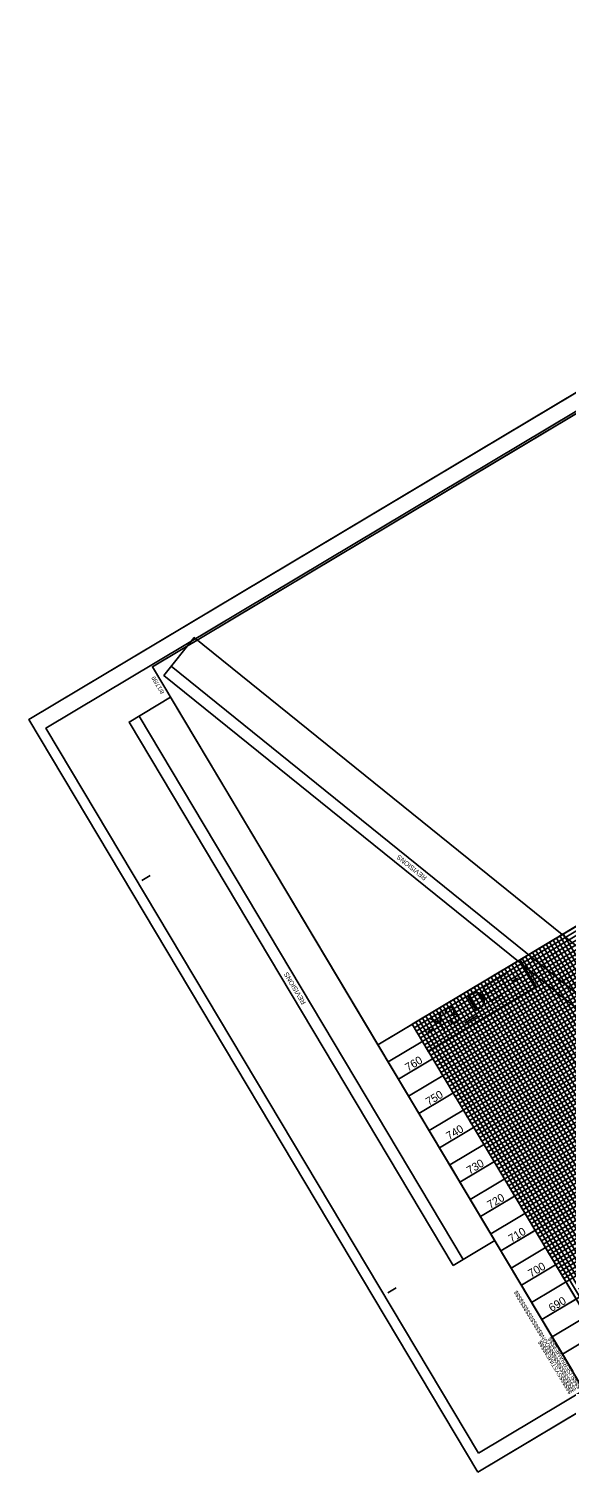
# Model space of a CAD drawing. Extents: x 1487794 to 1489801, y 498102 to 499906.
# Drawn here: x 1487794 to 1488466, y 498102 to 499906 of the extents above; entities that cross this region are included whole.
import ezdxf

# ---------------------------------------------------------------- set-up
doc = ezdxf.new("R2010")
doc.units = 0
for name, color, linetype in [('Exist Vertical Profile Ground Line', 7, 'Continuous'), ('Exist Vertical Profile Horizontal Axis Label Major', 7, 'Continuous'), ('Exist Vertical Profile Vertical Axis Label', 7, 'Continuous'), ('Prop Horizontal Alignment Curve and Spiral Data', 7, 'Continuous'), ('Prop Terminator CELL', 7, 'Continuous'), ('Prop Vertical Profile Curve Label', 7, 'Continuous'), ('Scratch_Level_6', 7, 'Continuous'), ('Sheet Data Field CELL', 7, 'Continuous'), ('Sheet DOT Grid CELL', 7, 'Continuous'), ('Sheet Layout Profile Border Port 2', 7, 'Continuous'), ('Sheet Plot Border Inside CELL', 7, 'Continuous'), ('Sheet Plot Border Outside CELL', 7, 'Continuous'), ('Sheet Profile CELL', 7, 'Continuous'), ('Sheet Profile Grid Major CELL', 7, 'Continuous'), ('Sheet Profile Grid Middle CELL', 7, 'Continuous'), ('Sheet Sticker Incomplete CELL', 7, 'Continuous')]:
    doc.layers.add(name, color=color, linetype=linetype)

msp = doc.modelspace()

# ---------------------------------------------------------------- linework, layer by layer
at = {"layer": 'Exist Vertical Profile Ground Line'}
msp.add_lwpolyline([(1488356.6, 498126.2), (1489787, 498980.3), (1489246.1, 499886.1), (1487815.7, 499032)], close=True, dxfattribs=at)
at = {"layer": 'Exist Vertical Profile Horizontal Axis Label Major'}
msp.add_lwpolyline([(1488355.7, 498102.3), (1489801.1, 498965.4), (1489239.8, 499905.6), (1487794.3, 499042.5)], close=True, dxfattribs=at)
at = {"layer": 'Exist Vertical Profile Vertical Axis Label'}
for p, q in [((1489239.8, 499905.6), (1487794.3, 499042.5)), ((1487794.3, 499042.5), (1488355.7, 498102.3)), ((1488355.7, 498102.3), (1489801.1, 498965.4))]:
    msp.add_line(p, q, dxfattribs=at)
at = {"layer": 'Prop Horizontal Alignment Curve and Spiral Data'}
msp.add_lwpolyline([(1488273.7, 498661.9), (1489475.7, 499379.7), (1489719.2, 498971.8), (1488517.2, 498254.1)], close=True, dxfattribs=at)
at = {"layer": 'Prop Terminator CELL'}
msp.add_lwpolyline([(1488230.8, 498636.3), (1487948.8, 499108.5), (1489064.9, 499775), (1489153.9, 499626), (1489135, 499614.7), (1489151.4, 499587.3), (1489342, 499701.1), (1489518.7, 499405.3)], close=True, dxfattribs=at)
at = {"layer": 'Prop Vertical Profile Curve Label'}
msp.add_lwpolyline([(1488293.7, 498628.4), (1488428.7, 498709), (1488408.7, 498742.5), (1488273.7, 498661.9)], close=True, dxfattribs=at)
at = {"layer": 'Scratch_Level_6'}
for p, q in [((1488587.8, 498612.8), (1487972.3, 499109.2)), ((1488337.4, 498368), (1487932.1, 499046.9))]:
    msp.add_line(p, q, dxfattribs=at)
for points in [[(1488578.7, 498601.5), (1487963.2, 499097.8), (1488001.2, 499145), (1488616.7, 498648.6)], [(1488324.9, 498360.6), (1487919.6, 499039.4), (1487971.5, 499070.5), (1488376.9, 498391.6)]]:
    msp.add_lwpolyline(points, close=True, dxfattribs=at)
at = {"layer": 'Sheet Data Field CELL'}
msp.add_line((1488273.7, 498661.9), (1488316.6, 498687.6), dxfattribs=at)
for points in [[(1488230.8, 498636.3), (1489518.7, 499405.3)], [(1489544.3, 499362.4), (1488256.4, 498593.4), (1488282, 498550.4), (1489569.9, 499319.5)], [(1489595.6, 499276.5), (1488307.7, 498507.5), (1488333.3, 498464.6), (1489621.2, 499233.6)], [(1489646.8, 499190.7), (1488358.9, 498421.7), (1488384.6, 498378.7), (1489672.5, 499147.7)], [(1489698.1, 499104.8), (1488410.2, 498335.8), (1488435.8, 498292.9), (1489723.7, 499061.9)], [(1489749.4, 499018.9), (1488461.5, 498249.9)], [(1488688.9, 498356.6), (1488445.4, 498764.5), (1488488.4, 498790.1), (1488731.9, 498382.3)], [(1488603.1, 498305.4), (1488359.6, 498713.2), (1488402.5, 498738.8), (1488646, 498331)], [(1488517.2, 498254.1), (1488273.7, 498661.9), (1488316.6, 498687.6), (1488560.2, 498279.7)], [(1488230.8, 498636.3), (1488474.3, 498228.5)]]:
    msp.add_lwpolyline(points, dxfattribs=at)
at = {"layer": 'Sheet Plot Border Inside CELL'}
for p, q in [((1488243.6, 498614.8), (1489531.5, 499383.8)), ((1489557.1, 499340.9), (1488269.2, 498571.9)), ((1488294.9, 498529), (1489582.7, 499298)), ((1489608.4, 499255.1), (1488320.5, 498486.1)), ((1488346.1, 498443.1), (1489634, 499212.1)), ((1489659.6, 499169.2), (1488371.8, 498400.2)), ((1488397.4, 498357.3), (1489685.3, 499126.3)), ((1489710.9, 499083.3), (1488423, 498314.3)), ((1488448.7, 498271.4), (1489736.5, 499040.4)), ((1488269.2, 498571.9), (1488294.9, 498529)), ((1488320.5, 498486.1), (1488346.1, 498443.1)), ((1488371.8, 498400.2), (1488397.4, 498357.3)), ((1488423, 498314.3), (1488448.7, 498271.4))]:
    msp.add_line(p, q, dxfattribs=at)
for points in [[(1488624.5, 498318.2), (1488381, 498726), (1488424, 498751.7), (1488667.5, 498343.8)], [(1488538.7, 498266.9), (1488295.2, 498674.8), (1488338.1, 498700.4), (1488581.6, 498292.6)]]:
    msp.add_lwpolyline(points, dxfattribs=at)
at = {"layer": 'Sheet Plot Border Outside CELL'}
for p, q in [((1488230.8, 498636.3), (1489518.7, 499405.3)), ((1488256.4, 498593.4), (1489544.3, 499362.4)), ((1488282, 498550.4), (1489569.9, 499319.5)), ((1488307.7, 498507.5), (1489595.6, 499276.5)), ((1488333.3, 498464.6), (1489621.2, 499233.6)), ((1488358.9, 498421.7), (1489646.8, 499190.7)), ((1488384.6, 498378.7), (1489672.5, 499147.7)), ((1488410.2, 498335.8), (1489698.1, 499104.8)), ((1488435.8, 498292.9), (1489723.7, 499061.9)), ((1488461.5, 498249.9), (1489749.4, 499018.9)), ((1488445.4, 498764.5), (1488688.9, 498356.6)), ((1488402.5, 498738.8), (1488646, 498331)), ((1488359.6, 498713.2), (1488603.1, 498305.4)), ((1488316.6, 498687.6), (1488560.2, 498279.7)), ((1488273.7, 498661.9), (1488517.2, 498254.1))]:
    msp.add_line(p, q, dxfattribs=at)
at = {"layer": 'Sheet Profile CELL'}
msp.add_lwpolyline([(1488273.7, 498661.9), (1489475.7, 499379.7), (1489719.2, 498971.8), (1488517.2, 498254.1)], close=True, dxfattribs=at)
at = {"layer": 'Sheet Profile Grid Major CELL'}
for points in [[(1489478.3, 499375.4), (1488276.3, 498657.6)], [(1489483.4, 499366.8), (1488281.4, 498649.1), (1488278.8, 498653.4), (1489480.9, 499371.1)], [(1489491.1, 499353.9), (1488289.1, 498636.2), (1488286.5, 498640.5), (1488284, 498644.8), (1489486, 499362.5)], [(1489496.2, 499345.3), (1488294.2, 498627.6), (1488291.7, 498631.9), (1489493.7, 499349.6)], [(1489503.9, 499332.5), (1488301.9, 498614.7), (1488299.3, 498619), (1488296.8, 498623.3), (1489498.8, 499341)], [(1489509.1, 499323.9), (1488307, 498606.1), (1488304.5, 498610.4), (1489506.5, 499328.2)], [(1489516.7, 499311), (1488314.7, 498593.3), (1488312.2, 498597.5), (1488309.6, 498601.8), (1489511.6, 499319.6)], [(1489521.9, 499302.4), (1488319.8, 498584.7), (1488317.3, 498589), (1489519.3, 499306.7)], [(1488327.5, 498571.8), (1488325, 498576.1), (1488322.4, 498580.4), (1489524.4, 499298.1)], [(1489532.1, 499285.2), (1488330.1, 498567.5), (1488327.5, 498571.8), (1489529.6, 499289.5)], [(1489537.3, 499276.6), (1488335.2, 498558.9), (1488332.7, 498563.2), (1489534.7, 499280.9)], [(1489544.9, 499263.8), (1488342.9, 498546), (1488340.4, 498550.3), (1489542.4, 499268.1)], [(1489550.1, 499255.2), (1488348, 498537.4), (1488345.5, 498541.7), (1489547.5, 499259.5)], [(1489557.8, 499242.3), (1488355.7, 498524.6), (1488353.2, 498528.9), (1489555.2, 499246.6)], [(1489562.9, 499233.7), (1488360.9, 498516), (1488358.3, 498520.3), (1489560.3, 499238)], [(1489570.6, 499220.8), (1488368.6, 498503.1), (1488366, 498507.4), (1489568, 499225.1)], [(1489575.7, 499212.3), (1488373.7, 498494.5), (1488371.1, 498498.8), (1489573.1, 499216.5)], [(1489583.4, 499199.4), (1488381.4, 498481.6), (1488378.8, 498485.9), (1489580.8, 499203.7)], [(1489588.5, 499190.8), (1488386.5, 498473.1), (1488383.9, 498477.3), (1489586, 499195.1)], [(1489596.2, 499177.9), (1488394.2, 498460.2), (1488391.6, 498464.5), (1489593.6, 499182.2)], [(1489601.3, 499169.3), (1488399.3, 498451.6), (1488396.7, 498455.9), (1489598.8, 499173.6)], [(1489609, 499156.4), (1488407, 498438.7), (1488404.4, 498443), (1489606.5, 499160.7)], [(1489614.2, 499147.9), (1488412.1, 498430.1), (1488409.6, 498434.4), (1489611.6, 499152.2)], [(1489621.8, 499135), (1488419.8, 498417.2), (1488417.3, 498421.5), (1489619.3, 499139.3)], [(1489627, 499126.4), (1488424.9, 498408.7), (1488422.4, 498413), (1489624.4, 499130.7)], [(1489634.7, 499113.5), (1488432.6, 498395.8), (1488430.1, 498400.1), (1489632.1, 499117.8)], [(1489639.8, 499104.9), (1488437.8, 498387.2), (1488435.2, 498391.5), (1489637.2, 499109.2)], [(1489647.5, 499092.1), (1488445.5, 498374.3), (1488442.9, 498378.6), (1489644.9, 499096.3)], [(1489652.6, 499083.5), (1488450.6, 498365.7), (1488448, 498370), (1489650, 499087.8)], [(1489660.3, 499070.6), (1488458.3, 498352.9), (1488455.7, 498357.1), (1489657.7, 499074.9)], [(1489665.4, 499062), (1488463.4, 498344.3), (1488460.8, 498348.6), (1489662.9, 499066.3)], [(1488701.8, 498364.3), (1488458.3, 498772.2), (1488462.6, 498774.7), (1488706.1, 498366.9)], [(1488671.8, 498346.4), (1488428.3, 498754.2), (1488432.5, 498756.8), (1488676.1, 498349)], [(1488680.4, 498351.5), (1488436.8, 498759.3), (1488441.1, 498761.9), (1488684.7, 498354.1)], [(1488693.2, 498359.2), (1488449.7, 498767), (1488454, 498769.6), (1488697.5, 498361.8)], [(1488650.3, 498333.6), (1488406.8, 498741.4), (1488411.1, 498744), (1488654.6, 498336.1)], [(1488658.9, 498338.7), (1488415.4, 498746.5), (1488419.7, 498749.1), (1488663.2, 498341.3)], [(1488616, 498313.1), (1488372.4, 498720.9), (1488376.7, 498723.5), (1488620.3, 498315.6)], [(1488628.8, 498320.8), (1488385.3, 498728.6), (1488389.6, 498731.2), (1488633.1, 498323.3)], [(1488637.4, 498325.9), (1488393.9, 498733.7), (1488398.2, 498736.3), (1488641.7, 498328.4)], [(1488585.9, 498295.1), (1488342.4, 498703), (1488346.7, 498705.5), (1488590.2, 498297.7)], [(1488594.5, 498300.3), (1488351, 498708.1), (1488355.3, 498710.6), (1488598.8, 498302.8)], [(1488607.4, 498307.9), (1488363.9, 498715.8), (1488368.2, 498718.3), (1488611.7, 498310.5)], [(1488551.6, 498274.6), (1488308.1, 498682.4), (1488312.3, 498685), (1488555.9, 498277.2)], [(1488564.4, 498282.3), (1488320.9, 498690.1), (1488325.2, 498692.7), (1488568.7, 498284.9)], [(1488573, 498287.4), (1488329.5, 498695.3), (1488333.8, 498697.8), (1488577.3, 498290)], [(1488521.5, 498256.7), (1488278, 498664.5), (1488282.3, 498667.1), (1488525.8, 498259.2)], [(1488530.1, 498261.8), (1488286.6, 498669.6), (1488290.9, 498672.2), (1488534.4, 498264.4)], [(1488543, 498269.5), (1488299.5, 498677.3), (1488303.8, 498679.9), (1488547.3, 498272.1)]]:
    msp.add_lwpolyline(points, dxfattribs=at)
at = {"layer": 'Sheet Profile Grid Middle CELL'}
for p, q in [((1488230.8, 498636.3), (1489518.7, 499405.3)), ((1487935.4, 498841.4), (1487946.1, 498847.8)), ((1488243, 498326.2), (1488253.7, 498332.6))]:
    msp.add_line(p, q, dxfattribs=at)
msp.add_lwpolyline([(1489236.7, 499877.5), (1487948.8, 499108.5), (1488487.1, 498207), (1489775, 498976)], close=True, dxfattribs=at)

# ---------------------------------------------------------------- texts
at = {"layer": 'Scratch_Level_6'}
for rotation, p in [(141.1156, (1488292.5, 498845.8)), (120.8418, (1488141.1, 498688.9))]:
    msp.add_text('REVISIONS', height=6, rotation=rotation, dxfattribs=at).set_placement(p)
at = {"layer": 'Sheet DOT Grid CELL'}
for s, p in [('$$$$$$$$$$$$$$$$DGN$$$$$$$$$$$$$$$$', (1488479.3, 498205.1)), ('$$$$USERNAME$$$$', (1488485, 498208.5)), ('$$$$$$SYSTIME$$$$$', (1488474.1, 498202))]:
    msp.add_text(s, height=5.25, rotation=120.8418, dxfattribs=at).set_placement(p)
at = {"layer": 'Sheet Layout Profile Border Port 2'}
msp.add_text('-Y3_DET-', height=22.5, rotation=30.8418, dxfattribs=at).set_placement((1488296.5, 498644.1))
at = {"layer": 'Sheet Profile Grid Middle CELL'}
msp.add_text('8/17/99', height=5.25, rotation=120.8418, dxfattribs=at).set_placement((1487964.1, 499076.6))
at = {"layer": 'Sheet Sticker Incomplete CELL'}
for s, p in [('760', (1488268.5, 498602.8)), ('750', (1488294.2, 498559.9)), ('740', (1488319.8, 498517)), ('730', (1488345.4, 498474.1)), ('720', (1488371.1, 498431.1)), ('710', (1488397.7, 498388.8)), ('700', (1488422.3, 498345.3)), ('690', (1488448, 498302.3))]:
    msp.add_text(s, height=10, rotation=30.8418, dxfattribs=at).set_placement(p)

doc.saveas('drawing.dxf')
